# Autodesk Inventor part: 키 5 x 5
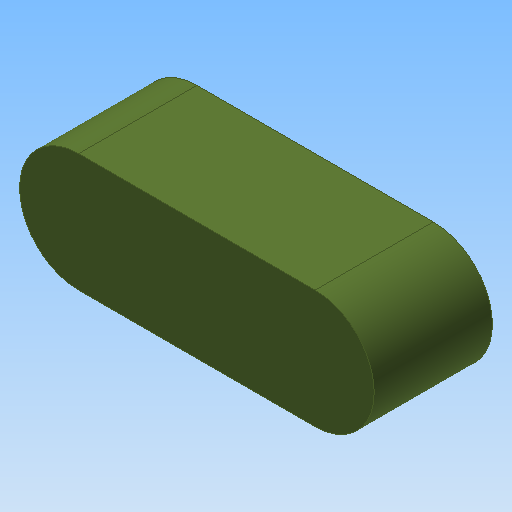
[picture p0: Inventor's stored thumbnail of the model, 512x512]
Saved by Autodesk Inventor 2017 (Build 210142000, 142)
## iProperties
Created: 2011-04
Part Number: 키 5 x 5
Document SubType Name: Modeling
Designer: pww
Density: 7.86 g/cm^3
Material: 강철, 연강
Appearance: 올리브 녹색
Author: pww
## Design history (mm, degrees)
sketch "스케치1"
  geometry: L1 (-5, -2.5)-(5, -2.5); L2 (5, 2.5)-(-5, 2.5); A1 r 2.5 centre (-5, 0) between (-5, 2.5) and (-5, -2.5); A2 r 2.5 centre (5, 0) between (5, -2.5) and (5, 2.5); 1 further point
  constraints: 4 end point, 4 point on circle, 2 centre point
extrude "돌출1" new body sketch "스케치1" distance "d0" = 5; taper "d1" = 0 deg
node "솔리드1"
